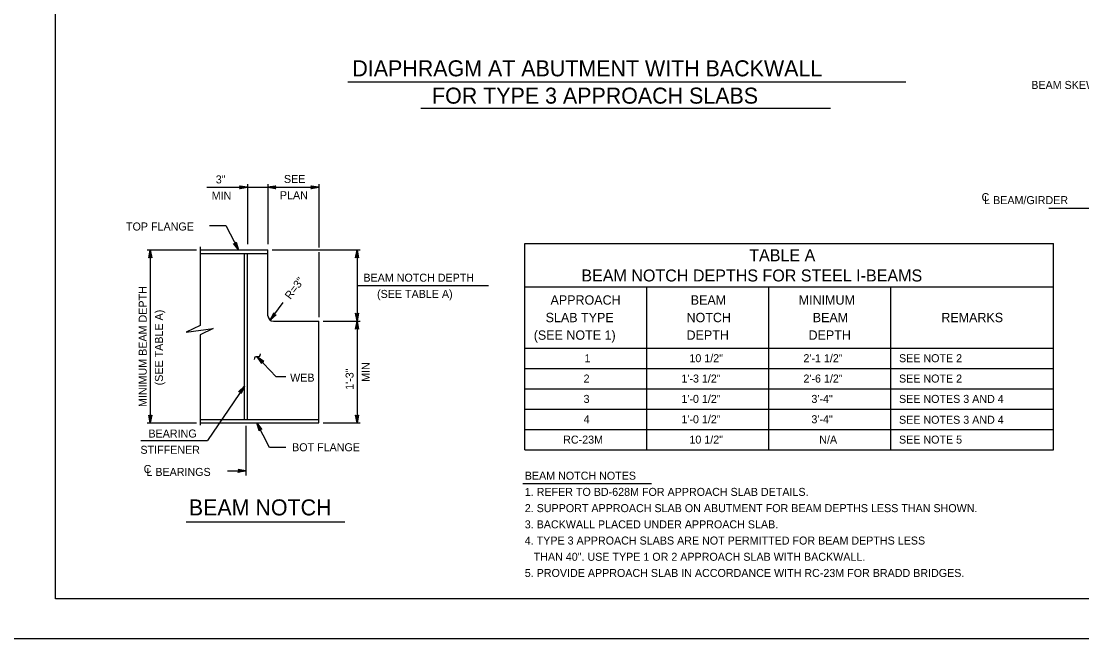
# Model space of a CAD drawing. Extents: x 640009 to 641706, y 298547 to 299735.
# Drawn here: x 640877.6 to 641275, y 299141.2 to 299372.4 of the extents above; entities that cross this region are included whole.
import ezdxf

# ---------------------------------------------------------------- set-up
doc = ezdxf.new("R2010")
doc.units = 0
doc.layers.add('1', color=7, linetype='Continuous')
doc.layers.add('PLT-BNDY', color=7, linetype='Continuous')

msp = doc.modelspace()

# ---------------------------------------------------------------- linework, layer by layer
at = {"layer": '1'}
for p, q in [((640890.47, 299156.17), (640890.47, 299720.17)), ((640890.47, 299156.17), (640890.47, 299720.17)), ((641000.01, 299349.78), (641209.12, 299349.78)), ((641027.3, 299339.83), (641180.9, 299339.83)), ((640947.13, 299310.23), (640989.09, 299310.23)), ((640962.42, 299311.43), (640962.42, 299288.99)), ((640970.04, 299311.43), (640970.04, 299288.99)), ((640989.09, 299311.43), (640989.09, 299287.71)), ((641262.69, 299302.38), (641297.34, 299302.38)), ((640948.09, 299295.88), (640954.21, 299295.88)), ((640954.21, 299295.88), (640958.97, 299286.75)), ((641066.32, 299211.94), (641066.32, 299289.23)), ((641066.32, 299289.23), (641264.44, 299289.23)), ((641264.44, 299211.94), (641264.44, 299289.23)), ((640924.78, 299286.75), (640943.22, 299286.75)), ((640925.95, 299286.75), (640925.95, 299221.98)), ((640944.62, 299287.98), (640944.62, 299258.54)), ((640944.62, 299286.75), (640970.04, 299286.75)), ((640944.62, 299285.48), (640970.04, 299285.48)), ((640961.2, 299223.25), (640961.2, 299285.48)), ((640962.42, 299223.25), (640962.42, 299285.48)), ((640970.04, 299262.11), (640970.04, 299286.75)), ((640971.65, 299286.75), (641004.58, 299286.75)), ((640989.09, 299286), (640989.09, 299261.64)), ((641003.42, 299286.75), (641003.42, 299260.08)), ((641003.42, 299273.41), (641052.75, 299273.41)), ((641066.32, 299272.9), (641264.44, 299272.9)), ((641112.04, 299211.94), (641112.04, 299272.9)), ((641157.76, 299211.94), (641157.76, 299272.9)), ((641203.48, 299211.94), (641203.48, 299272.9)), ((640970.85, 299260.49), (640975.81, 299267.1)), ((640972.07, 299260.08), (640989.09, 299260.08)), ((640989.09, 299221.98), (640989.09, 299260.08)), ((640990.74, 299260.08), (641004.58, 299260.08)), ((641003.42, 299260.08), (641003.42, 299221.98)), ((640944.62, 299255.02), (640944.62, 299221.22)), ((641066.32, 299250.04), (641264.44, 299250.04)), ((640965.99, 299246.74), (640973.07, 299239.29)), ((641066.32, 299242.42), (641264.44, 299242.42)), ((640976.78, 299239.29), (640973.07, 299239.29)), ((640961.2, 299235.82), (640947.43, 299215.36)), ((641066.32, 299234.8), (641264.44, 299234.8)), ((641066.32, 299227.18), (641264.44, 299227.18)), ((640924.78, 299221.98), (640943.22, 299221.98)), ((640944.62, 299223.25), (640989.09, 299223.25)), ((640944.62, 299221.98), (640989.09, 299221.98)), ((640970.68, 299212.84), (640965.92, 299221.98)), ((640990.74, 299221.98), (641004.58, 299221.98)), ((640961.81, 299220.97), (640961.81, 299202.28)), ((641066.32, 299219.56), (641264.44, 299219.56)), ((640922.42, 299215.36), (640947.43, 299215.36)), ((640976.8, 299212.84), (640970.68, 299212.84)), ((641066.32, 299211.94), (641264.44, 299211.94)), ((640954.88, 299204.03), (640961.81, 299204.03)), ((641065.53, 299199.34), (641113.83, 299199.34)), ((640939.4, 299184.96), (640998.91, 299184.96)), ((641676.47, 299156.17), (640890.47, 299156.17)), ((641676.47, 299156.17), (640890.47, 299156.17))]:
    msp.add_line(p, q, dxfattribs=at)
for points in [[(640962.42, 299310.23), (640959.44, 299309.67), (640959.55, 299309.75), (640959.67, 299309.83), (640959.73, 299309.93), (640959.78, 299310.03), (640959.8, 299310.13), (640959.82, 299310.23), (640959.8, 299310.33), (640959.78, 299310.43), (640959.73, 299310.53), (640959.67, 299310.63), (640959.55, 299310.71), (640959.44, 299310.79), (640962.42, 299310.23), (640959.55, 299310.71), (640959.67, 299310.63), (640962.42, 299310.23), (640959.73, 299310.53), (640959.78, 299310.43), (640962.42, 299310.23), (640959.8, 299310.33), (640959.82, 299310.23), (640962.42, 299310.23), (640959.8, 299310.13), (640959.78, 299310.03), (640962.42, 299310.23), (640959.73, 299309.93), (640959.67, 299309.83), (640962.42, 299310.23), (640959.55, 299309.75)], [(640970.04, 299310.23), (640973.02, 299310.79), (640972.91, 299310.71), (640972.79, 299310.63), (640972.73, 299310.53), (640972.67, 299310.43), (640972.66, 299310.33), (640972.64, 299310.23), (640972.66, 299310.13), (640972.67, 299310.03), (640972.73, 299309.93), (640972.79, 299309.83), (640972.91, 299309.75), (640973.02, 299309.67), (640970.04, 299310.23), (640972.91, 299309.75), (640972.79, 299309.83), (640970.04, 299310.23), (640972.73, 299309.93), (640972.67, 299310.03), (640970.04, 299310.23), (640972.66, 299310.13), (640972.64, 299310.23), (640970.04, 299310.23), (640972.66, 299310.33), (640972.67, 299310.43), (640970.04, 299310.23), (640972.73, 299310.53), (640972.79, 299310.63), (640970.04, 299310.23), (640972.91, 299310.71)], [(640989.09, 299310.23), (640986.11, 299309.67), (640986.22, 299309.75), (640986.34, 299309.83), (640986.4, 299309.93), (640986.45, 299310.03), (640986.47, 299310.13), (640986.49, 299310.23), (640986.47, 299310.33), (640986.45, 299310.43), (640986.4, 299310.53), (640986.34, 299310.63), (640986.22, 299310.71), (640986.11, 299310.79), (640989.09, 299310.23), (640986.22, 299310.71), (640986.34, 299310.63), (640989.09, 299310.23), (640986.4, 299310.53), (640986.45, 299310.43), (640989.09, 299310.23), (640986.47, 299310.33), (640986.49, 299310.23), (640989.09, 299310.23), (640986.47, 299310.13), (640986.45, 299310.03), (640989.09, 299310.23), (640986.4, 299309.93), (640986.34, 299309.83), (640989.09, 299310.23), (640986.22, 299309.75)], [(640958.97, 299286.75), (640957.1, 299289.14), (640957.22, 299289.07), (640957.35, 299289), (640957.46, 299289), (640957.58, 299288.99), (640957.68, 299289.02), (640957.77, 299289.05), (640957.85, 299289.12), (640957.93, 299289.18), (640958, 299289.28), (640958.06, 299289.37), (640958.07, 299289.51), (640958.09, 299289.65), (640958.97, 299286.75), (640958.07, 299289.51), (640958.06, 299289.37), (640958.97, 299286.75), (640958, 299289.28), (640957.93, 299289.18), (640958.97, 299286.75), (640957.85, 299289.12), (640957.77, 299289.05), (640958.97, 299286.75), (640957.68, 299289.02), (640957.58, 299288.99), (640958.97, 299286.75), (640957.46, 299289), (640957.35, 299289), (640958.97, 299286.75), (640957.22, 299289.07)], [(640925.95, 299286.75), (640926.51, 299283.77), (640926.43, 299283.88), (640926.35, 299284), (640926.25, 299284.05), (640926.15, 299284.11), (640926.05, 299284.13), (640925.95, 299284.15), (640925.85, 299284.13), (640925.75, 299284.11), (640925.65, 299284.05), (640925.55, 299284), (640925.47, 299283.88), (640925.39, 299283.77), (640925.95, 299286.75), (640925.47, 299283.88), (640925.55, 299284), (640925.95, 299286.75), (640925.65, 299284.05), (640925.75, 299284.11), (640925.95, 299286.75), (640925.85, 299284.13), (640925.95, 299284.15), (640925.95, 299286.75), (640926.05, 299284.13), (640926.15, 299284.11), (640925.95, 299286.75), (640926.25, 299284.05), (640926.35, 299284), (640925.95, 299286.75), (640926.43, 299283.88)], [(641003.42, 299286.75), (641003.98, 299283.77), (641003.9, 299283.88), (641003.82, 299284), (641003.72, 299284.05), (641003.62, 299284.11), (641003.52, 299284.13), (641003.42, 299284.15), (641003.32, 299284.13), (641003.22, 299284.11), (641003.12, 299284.05), (641003.02, 299284), (641002.94, 299283.88), (641002.87, 299283.77), (641003.42, 299286.75), (641002.94, 299283.88), (641003.02, 299284), (641003.42, 299286.75), (641003.12, 299284.05), (641003.22, 299284.11), (641003.42, 299286.75), (641003.32, 299284.13), (641003.42, 299284.15), (641003.42, 299286.75), (641003.52, 299284.13), (641003.62, 299284.11), (641003.42, 299286.75), (641003.72, 299284.05), (641003.82, 299284), (641003.42, 299286.75), (641003.9, 299283.88)], [(640970.85, 299260.49), (640972.24, 299263.18), (640972.23, 299263.04), (640972.22, 299262.91), (640972.27, 299262.8), (640972.31, 299262.69), (640972.38, 299262.61), (640972.45, 299262.54), (640972.54, 299262.49), (640972.62, 299262.44), (640972.74, 299262.43), (640972.86, 299262.41), (640972.99, 299262.46), (640973.12, 299262.5), (640970.85, 299260.49), (640972.99, 299262.46), (640972.86, 299262.41), (640970.85, 299260.49), (640972.74, 299262.43), (640972.62, 299262.44), (640970.85, 299260.49), (640972.54, 299262.49), (640972.45, 299262.54), (640970.85, 299260.49), (640972.38, 299262.61), (640972.31, 299262.69), (640970.85, 299260.49), (640972.27, 299262.8), (640972.22, 299262.91), (640970.85, 299260.49), (640972.23, 299263.04)], [(641003.42, 299260.08), (641002.87, 299263.06), (641002.94, 299262.95), (641003.02, 299262.83), (641003.12, 299262.77), (641003.22, 299262.71), (641003.32, 299262.7), (641003.42, 299262.68), (641003.52, 299262.7), (641003.62, 299262.71), (641003.72, 299262.77), (641003.82, 299262.83), (641003.9, 299262.95), (641003.98, 299263.06), (641003.42, 299260.08), (641003.9, 299262.95), (641003.82, 299262.83), (641003.42, 299260.08), (641003.72, 299262.77), (641003.62, 299262.71), (641003.42, 299260.08), (641003.52, 299262.7), (641003.42, 299262.68), (641003.42, 299260.08), (641003.32, 299262.7), (641003.22, 299262.71), (641003.42, 299260.08), (641003.12, 299262.77), (641003.02, 299262.83), (641003.42, 299260.08), (641002.94, 299262.95)], [(640944.62, 299258.54), (640939.43, 299256), (640949.58, 299257.38), (640944.62, 299255.02)], [(641003.42, 299260.08), (641003.98, 299257.1), (641003.9, 299257.21), (641003.82, 299257.33), (641003.72, 299257.38), (641003.62, 299257.44), (641003.52, 299257.46), (641003.42, 299257.48), (641003.32, 299257.46), (641003.22, 299257.44), (641003.12, 299257.38), (641003.02, 299257.33), (641002.94, 299257.21), (641002.87, 299257.1), (641003.42, 299260.08), (641002.94, 299257.21), (641003.02, 299257.33), (641003.42, 299260.08), (641003.12, 299257.38), (641003.22, 299257.44), (641003.42, 299260.08), (641003.32, 299257.46), (641003.42, 299257.48), (641003.42, 299260.08), (641003.52, 299257.46), (641003.62, 299257.44), (641003.42, 299260.08), (641003.72, 299257.38), (641003.82, 299257.33), (641003.42, 299260.08), (641003.9, 299257.21)], [(640965.99, 299246.74), (640967.64, 299244.19), (640967.61, 299244.33), (640967.59, 299244.47), (640967.62, 299244.58), (640967.66, 299244.69), (640967.72, 299244.78), (640967.78, 299244.86), (640967.86, 299244.91), (640967.95, 299244.97), (640968.06, 299245), (640968.17, 299245.02), (640968.31, 299244.99), (640968.45, 299244.96), (640965.99, 299246.74), (640968.31, 299244.99), (640968.17, 299245.02), (640965.99, 299246.74), (640968.06, 299245), (640967.95, 299244.97), (640965.99, 299246.74), (640967.86, 299244.91), (640967.78, 299244.86), (640965.99, 299246.74), (640967.72, 299244.78), (640967.66, 299244.69), (640965.99, 299246.74), (640967.62, 299244.58), (640967.59, 299244.47), (640965.99, 299246.74), (640967.61, 299244.33)], [(640961.2, 299235.82), (640959.97, 299233.05), (640959.97, 299233.19), (640959.97, 299233.33), (640959.92, 299233.43), (640959.87, 299233.54), (640959.8, 299233.61), (640959.73, 299233.68), (640959.64, 299233.72), (640959.54, 299233.77), (640959.43, 299233.77), (640959.31, 299233.78), (640959.18, 299233.73), (640959.05, 299233.68), (640961.2, 299235.82), (640959.18, 299233.73), (640959.31, 299233.78), (640961.2, 299235.82), (640959.43, 299233.77), (640959.54, 299233.77), (640961.2, 299235.82), (640959.64, 299233.72), (640959.73, 299233.68), (640961.2, 299235.82), (640959.8, 299233.61), (640959.87, 299233.54), (640961.2, 299235.82), (640959.92, 299233.43), (640959.97, 299233.33), (640961.2, 299235.82), (640959.97, 299233.19)], [(640925.95, 299221.98), (640925.39, 299224.96), (640925.47, 299224.85), (640925.55, 299224.73), (640925.65, 299224.67), (640925.75, 299224.61), (640925.85, 299224.6), (640925.95, 299224.58), (640926.05, 299224.6), (640926.15, 299224.61), (640926.25, 299224.67), (640926.35, 299224.73), (640926.43, 299224.85), (640926.51, 299224.96), (640925.95, 299221.98), (640926.43, 299224.85), (640926.35, 299224.73), (640925.95, 299221.98), (640926.25, 299224.67), (640926.15, 299224.61), (640925.95, 299221.98), (640926.05, 299224.6), (640925.95, 299224.58), (640925.95, 299221.98), (640925.85, 299224.6), (640925.75, 299224.61), (640925.95, 299221.98), (640925.65, 299224.67), (640925.55, 299224.73), (640925.95, 299221.98), (640925.47, 299224.85)], [(640965.92, 299221.98), (640967.8, 299219.59), (640967.67, 299219.66), (640967.55, 299219.72), (640967.43, 299219.73), (640967.32, 299219.73), (640967.22, 299219.7), (640967.12, 299219.67), (640967.04, 299219.61), (640966.96, 299219.55), (640966.9, 299219.45), (640966.84, 299219.35), (640966.82, 299219.21), (640966.81, 299219.07), (640965.92, 299221.98), (640966.82, 299219.21), (640966.84, 299219.35), (640965.92, 299221.98), (640966.9, 299219.45), (640966.96, 299219.55), (640965.92, 299221.98), (640967.04, 299219.61), (640967.12, 299219.67), (640965.92, 299221.98), (640967.22, 299219.7), (640967.32, 299219.73), (640965.92, 299221.98), (640967.43, 299219.73), (640967.55, 299219.72), (640965.92, 299221.98), (640967.67, 299219.66)], [(641003.42, 299221.98), (641002.87, 299224.96), (641002.94, 299224.85), (641003.02, 299224.73), (641003.12, 299224.67), (641003.22, 299224.61), (641003.32, 299224.6), (641003.42, 299224.58), (641003.52, 299224.6), (641003.62, 299224.61), (641003.72, 299224.67), (641003.82, 299224.73), (641003.9, 299224.85), (641003.98, 299224.96), (641003.42, 299221.98), (641003.9, 299224.85), (641003.82, 299224.73), (641003.42, 299221.98), (641003.72, 299224.67), (641003.62, 299224.61), (641003.42, 299221.98), (641003.52, 299224.6), (641003.42, 299224.58), (641003.42, 299221.98), (641003.32, 299224.6), (641003.22, 299224.61), (641003.42, 299221.98), (641003.12, 299224.67), (641003.02, 299224.73), (641003.42, 299221.98), (641002.94, 299224.85)], [(640961.81, 299204.03), (640958.83, 299203.47), (640958.94, 299203.55), (640959.06, 299203.63), (640959.12, 299203.73), (640959.18, 299203.83), (640959.19, 299203.93), (640959.21, 299204.03), (640959.19, 299204.13), (640959.18, 299204.23), (640959.12, 299204.33), (640959.06, 299204.43), (640958.94, 299204.51), (640958.83, 299204.59), (640961.81, 299204.03), (640958.94, 299204.51), (640959.06, 299204.43), (640961.81, 299204.03), (640959.12, 299204.33), (640959.18, 299204.23), (640961.81, 299204.03), (640959.19, 299204.13), (640959.21, 299204.03), (640961.81, 299204.03), (640959.19, 299203.93), (640959.18, 299203.83), (640961.81, 299204.03), (640959.12, 299203.73), (640959.06, 299203.63), (640961.81, 299204.03), (640958.94, 299203.55)]]:
    msp.add_lwpolyline(points, dxfattribs=at)
msp.add_arc((640972.07, 299262.11), 2.03, 180, 270, dxfattribs=at)
msp.add_spline([(640967.1, 299247.84), (640966.79, 299246.91), (640965.18, 299246.57), (640964.85, 299245.69)], degree=3, dxfattribs=at)
at = {"layer": 'PLT-BNDY'}
msp.add_lwpolyline([(640850.47, 299735.17), (641691.47, 299735.17), (641691.47, 299141.17), (640850.47, 299141.17)], close=True, dxfattribs=at)

# ---------------------------------------------------------------- texts
at = {"layer": '1'}
for s, height, p in [('DIAPHRAGM AT ABUTMENT WITH BACKWALL', 6, (641001.68, 299351.78)), ('BEAM SKEW ANGLE', 3, (641256.1, 299347.06)), ('FOR TYPE 3 APPROACH SLABS', 6, (641031.54, 299341.55)), ('3"', 3, (640950.5, 299311.68)), ('SEE', 3, (640976.04, 299311.84)), ('MIN', 3, (640948.97, 299305.61)), ('PLAN', 3, (640974.53, 299305.77)), ('C', 3, (641237.47, 299305.04)), ('L BEAM/GIRDER', 3, (641238.44, 299303.93)), ('TOP FLANGE', 3, (640916.87, 299294.05)), ('TABLE A', 4.5, (641150.41, 299282.54)), ('BEAM NOTCH DEPTH', 3, (641005.82, 299274.88)), ('BEAM NOTCH DEPTHS FOR STEEL I-BEAMS', 4.5, (641087.5, 299274.96)), ('(SEE TABLE A)', 3, (641010.94, 299268.8)), ('APPROACH', 3.5, (641075.94, 299266.29)), ('BEAM', 3.5, (641128.48, 299266.29)), ('MINIMUM', 3.5, (641168.95, 299266.29)), ('SLAB TYPE', 3.5, (641074.11, 299259.72)), ('NOTCH', 3.5, (641126.91, 299259.72)), ('BEAM', 3.5, (641174.2, 299259.72)), ('REMARKS', 3.5, (641222.39, 299259.72)), ('(SEE NOTE 1)', 3.5, (641069.66, 299253.14)), ('DEPTH', 3.5, (641126.91, 299253.14)), ('DEPTH', 3.5, (641172.63, 299253.14)), ('1', 3, (641088.68, 299244.73)), ('10 1/2"', 3, (641127.99, 299244.73)), ('2\'-1 1/2"', 3, (641170.71, 299244.73)), ('SEE NOTE 2', 3, (641206.53, 299244.73)), ('WEB', 3, (640978.36, 299237.46)), ('2', 3, (641088.33, 299237.11)), ('1\'-3 1/2"', 3, (641124.99, 299237.11)), ('2\'-6 1/2"', 3, (641170.71, 299237.11)), ('SEE NOTE 2', 3, (641206.53, 299237.11)), ('3', 3, (641088.33, 299229.49)), ('1\'-0 1/2"', 3, (641124.99, 299229.49)), ('3\'-4"', 3, (641173.71, 299229.49)), ('SEE NOTES 3 AND 4', 3, (641206.53, 299229.49)), ('4', 3, (641088.33, 299221.87)), ('1\'-0 1/2"', 3, (641124.99, 299221.87)), ('3\'-4"', 3, (641173.71, 299221.87)), ('SEE NOTES 3 AND 4', 3, (641206.53, 299221.68)), ('BEARING', 3, (640925.27, 299216.52)), ('RC-23M', 3, (641080.68, 299214.25)), ('10 1/2"', 3, (641127.99, 299214.25)), ('N/A', 3, (641176.64, 299214.25)), ('SEE NOTE 5', 3, (641206.53, 299214.25)), ('STIFFENER', 3, (640922.27, 299210.44)), ('BOT FLANGE', 3, (640979.1, 299211.39)), ('C', 3, (640923.47, 299203.25)), ('L BEARINGS', 3, (640924.51, 299202.15)), ('BEAM NOTCH NOTES', 3, (641066.29, 299200.74)), ('1. REFER TO BD-628M FOR APPROACH SLAB DETAILS.', 3, (641066.29, 299194.67)), ('BEAM NOTCH', 6, (640940.39, 299187.37)), ('2. SUPPORT APPROACH SLAB ON ABUTMENT FOR BEAM DEPTHS LESS THAN SHOWN.', 3, (641066.29, 299188.59)), ('3. BACKWALL PLACED UNDER APPROACH SLAB.', 3, (641066.29, 299182.52)), ('4. TYPE 3 APPROACH SLABS ARE NOT PERMITTED FOR BEAM DEPTHS LESS', 3, (641066.29, 299176.45)), ('   THAN 40". USE TYPE 1 OR 2 APPROACH SLAB WITH BACKWALL.', 3, (641066.29, 299170.38)), ('5. PROVIDE APPROACH SLAB IN ACCORDANCE WITH RC-23M FOR BRADD BRIDGES.', 3, (641066.29, 299164.31))]:
    msp.add_text(s, height=height, dxfattribs=at).set_placement(p)
for s, rotation, p in [('R=3"', 53.1162, (640978.49, 299268.01)), ('MINIMUM BEAM DEPTH', 90, (640924.62, 299227.96)), ('(SEE TABLE A)', 90, (640930.7, 299236.07)), ('1\'-3"', 90, (641002.13, 299234.39)), ('MIN', 90, (641008.2, 299237.37))]:
    msp.add_text(s, height=3, rotation=rotation, dxfattribs=at).set_placement(p)

doc.saveas('drawing.dxf')
